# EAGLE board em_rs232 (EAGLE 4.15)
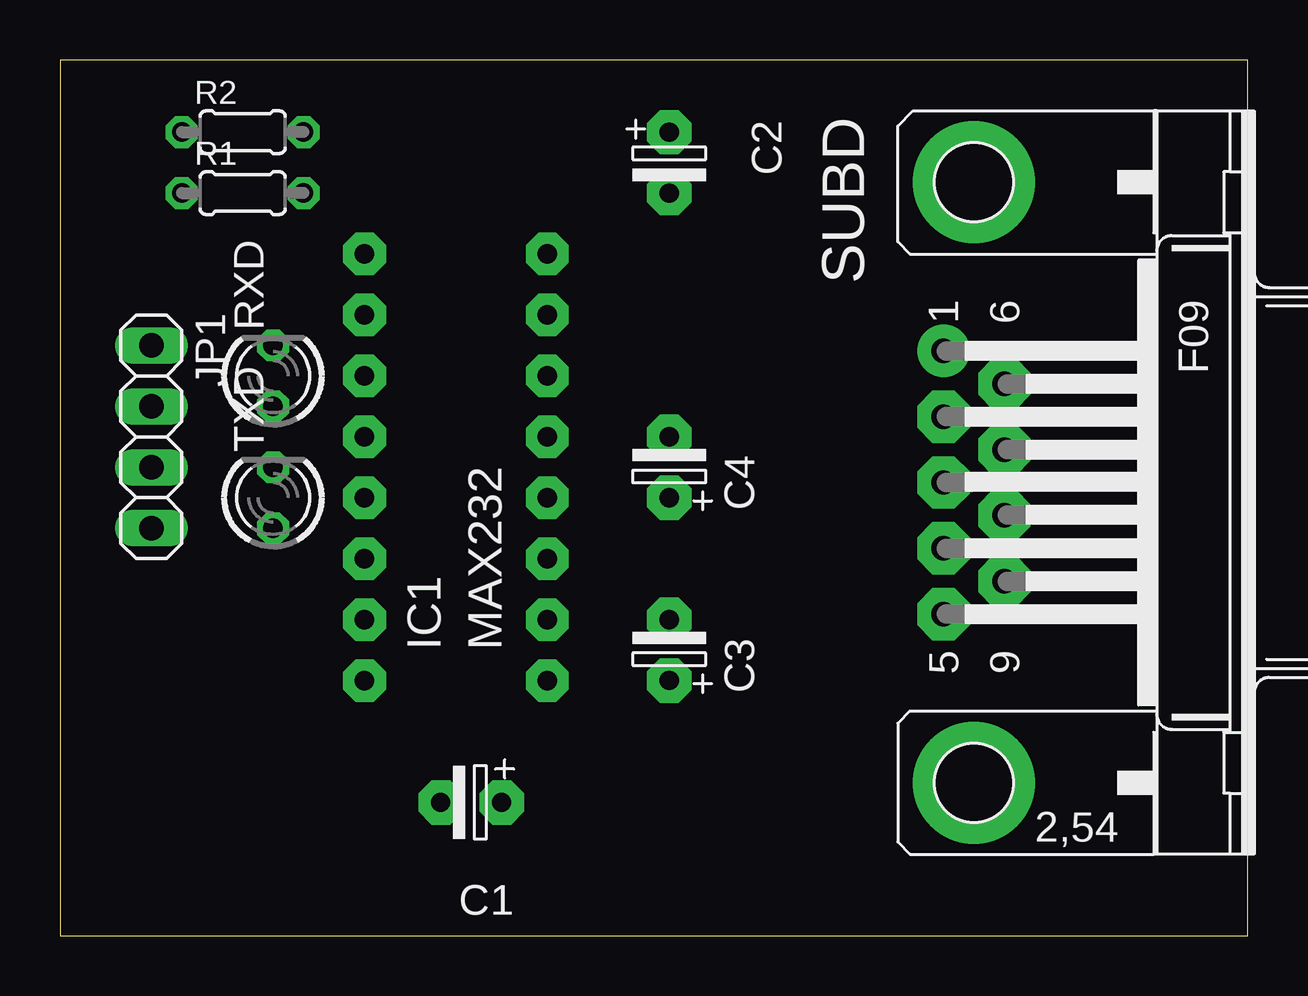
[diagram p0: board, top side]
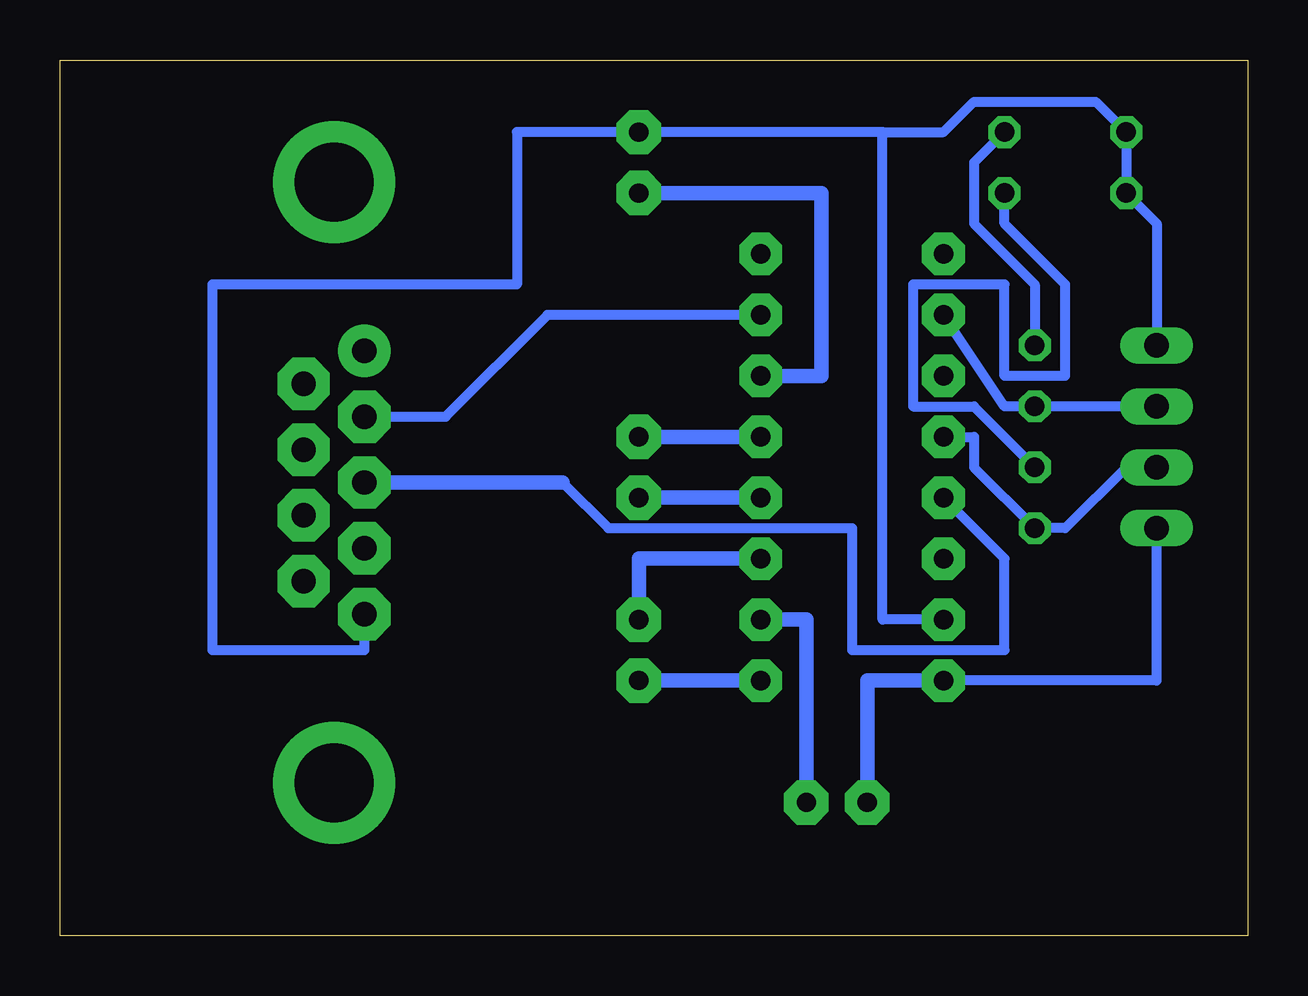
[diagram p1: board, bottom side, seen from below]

Size 49.52 x 36.5 mm. Coordinates in mm from the lower left corner, seen from the top.
Outline: 0,36.5 0,0 49.52,0 49.52,36.5 0,36.5
Copper layers (1*16): Top 0.035mm / dielectric 1.5mm / Bottom 0.035mm
Design rules "default": minimum track width 10mil, minimum drill 24mil, track to track 8mil, track to pad 8mil, pad to pad 8mil, via to via 8mil, smd to smd 8mil, copper to edge 40mil, drill to drill 8mil, minimum pad ring 10mil, minimum via ring 8mil, stop-mask expansion 0mil, vias tented up to drill 0mil, thermal gap 10mil

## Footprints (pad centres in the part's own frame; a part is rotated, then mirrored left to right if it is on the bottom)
ES-2,5 = drill 0.8 pad 1.85 octagon: 1 -1.27,0; 2 1.27,0
16PIN = drill 0.813 pad 1.778 octagon: 1 -8.89,-3.81; 2 -6.35,-3.81; 3 -3.81,-3.81; 4 -1.27,-3.81; 5 1.27,-3.81; 6 3.81,-3.81; 7 6.35,-3.81; 8 8.89,-3.81; 9 8.89,3.81; 10 6.35,3.81; 11 3.81,3.81; 12 1.27,3.81; 13 -1.27,3.81; 14 -3.81,3.81; 15 -6.35,3.81; 16 -8.89,3.81
1X04 = drill 1.016 long: 1 -3.81,0; 2 -1.27,0; 3 1.27,0; 4 3.81,0
0204/5 = drill 0.813 octagon: 1 -2.54,0; 2 2.54,0
LED3MM = drill 0.813 octagon: A -1.27,0; K 1.27,0
F09HP = drill 1.016 pad 2.184 round: 1 -5.486,-1.27 | drill 1.016 pad 2.184 octagon: 2 -2.743,-1.27; 3 0,-1.27; 4 2.743,-1.27; 5 5.486,-1.27; 6 -4.115,1.27; 7 -1.372,1.27; 8 1.372,1.27; 9 4.115,1.27 | drill 3.302 pad 5.08 round: G1 -12.522,0; G2 12.522,0

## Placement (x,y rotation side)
C1  1uF  [ES-2,5]  17.14,5.55 180 top
C2  1uF  [ES-2,5]  25.39,32.22 270 top
C3  1uF  [ES-2,5]  25.39,11.9 90 top
C4  1uF  [ES-2,5]  25.39,19.52 90 top
IC1  MAX232  [16PIN]  16.51,19.52 90 top
JP1  [1X04]  3.81,20.79 270 top
R1  1k  [0204/5]  7.62,30.95 0 top
R2  1k  [0204/5]  7.62,33.49 0 top
RXD  [LED3MM]  8.88,23.33 90 top
SUBD  [F09HP]  38.09,18.88 270 top
TXD  [LED3MM]  8.88,18.25 90 top

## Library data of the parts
C1-C4 = DISCRETE
IC1 = EIGENE
JP1 = pinhead
R1 R2 = rcl
RXD TXD = led
SUBD = SUBD-A

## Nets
C1+: C3.1 IC1.1
C1-: C3.2 IC1.3
C2+: C4.1 IC1.4
C2-: C4.2 IC1.5
GND: C2.1 IC1.15 JP1.1 R1.1 R2.1 SUBD.5
N$1: IC1.7 SUBD.2
N$2: IC1.12 JP1.3 TXD.A
N$3: IC1.10 JP1.2 RXD.A
N$4: R1.2 TXD.K
N$5: R2.2 RXD.K
R1IN: IC1.13 SUBD.3
V+: C1.1 IC1.2
V-: C2.2 IC1.6
VCC: C1.2 IC1.16 JP1.4

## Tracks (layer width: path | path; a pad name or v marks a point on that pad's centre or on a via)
C1+
  Bottom 0.61: IC1.1 C3.1
C1-
  Bottom 0.61: IC1.3 25.39,15.71 C3.2
C2+
  Bottom 0.61: IC1.4 C4.1
C2-
  Bottom 0.61: IC1.5 C4.2
GND
  Bottom 0.406: JP1.1 3.81,29.68 R1.1 R2.1 6.34,34.76 11.42,34.76 12.69,33.49 15.23,33.49 | SUBD.5 36.82,11.9 43.17,11.9 43.17,27.14 30.48,27.14 30.48,33.49 C2.1 15.23,33.49 | IC1.15 15.23,13.17 15.23,33.49
N$1
  Bottom 0.406: IC1.7 29.21,25.87 33.45,21.63 SUBD.2
N$2
  Bottom 0.406: JP1.3 5.08,19.52 7.62,16.98 TXD.A 11.42,19.52 11.42,20.79 IC1.12
N$3
  Bottom 0.406: JP1.2 RXD.A 10.15,22.06 IC1.10
N$4
  Bottom 0.406: R1.2 10.15,29.68 7.62,27.14 7.62,23.33 10.15,23.33 10.15,27.14 13.96,27.14 13.96,22.06 11.42,22.06 TXD.K
N$5
  Bottom 0.406: R2.2 11.42,32.22 11.42,29.68 8.88,27.14 RXD.K
R1IN
  Bottom 0.406: 28.57,18.88 26.67,16.98 16.51,16.98 16.51,11.9 10.15,11.9 10.15,15.71 IC1.13
  Bottom 0.61: 28.57,18.88 SUBD.3
V+
  Bottom 0.61: C1.1 18.41,13.17 IC1.2
V-
  Bottom 0.61: C2.2 17.78,30.95 17.78,23.33 IC1.6
VCC
  Bottom 0.406: JP1.4 3.81,10.63 IC1.16
  Bottom 0.61: IC1.16 15.87,10.63 C1.2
